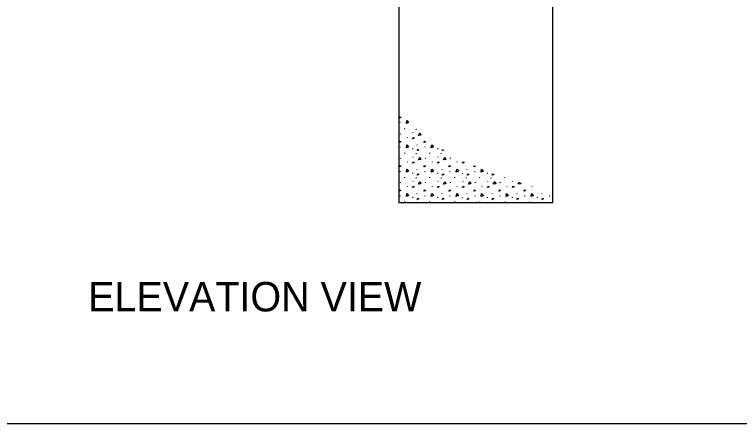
# Model space of a CAD drawing. Extents: x 99862 to 103680, y 99470 to 102076.
# Drawn here: x 100239 to 100829, y 100000 to 100332 of the extents above; entities that cross this region are included whole.
import ezdxf

# ---------------------------------------------------------------- set-up
doc = ezdxf.new("R2010")
doc.units = 0
for name, color, linetype in [('Level 1', 7, 'Continuous'), ('Level 12', 7, 'Continuous'), ('Level 20', 7, 'Continuous')]:
    doc.layers.add(name, color=color, linetype=linetype)

msp = doc.modelspace()

# ---------------------------------------------------------------- linework, layer by layer
at = {"layer": 'Level 1'}
msp.add_lwpolyline([(99862, 99999.5), (103151, 99999.5), (103151, 102075.5), (99862, 102075.5)], close=True, dxfattribs=at)
at = {"layer": 'Level 12'}
for p, q in [((100552.17, 100509.86), (100552.17, 100179.2)), ((100677.47, 100179.2), (100677.47, 100509.86)), ((100553.21, 100243.92), (100553.38, 100244.3)), ((100557.07, 100239), (100557.24, 100239.38)), ((100563.32, 100242.53), (100563.33, 100242.47)), ((100566.18, 100239), (100566.35, 100238.74)), ((100566.35, 100238.9), (100566.52, 100238.65)), ((100553.63, 100234.88), (100553.8, 100235.26)), ((100563.68, 100235.86), (100563.85, 100236.24)), ((100558.93, 100232.17), (100559.1, 100231.91)), ((100553.21, 100224.11), (100553.38, 100224.5)), ((100563.29, 100223.05), (100563.33, 100222.67)), ((100567.07, 100225.85), (100567.24, 100226.23)), ((100573.51, 100224.11), (100573.68, 100224.5)), ((100583.59, 100223.05), (100583.63, 100222.67)), ((100587.46, 100221.4), (100587.93, 100222.37)), ((100588.82, 100221.83), (100587.46, 100221.4)), ((100553.63, 100215.08), (100553.8, 100215.46)), ((100557.07, 100219.2), (100557.24, 100219.58)), ((100563.68, 100216.06), (100563.85, 100216.44)), ((100566.18, 100219.2), (100566.35, 100218.94)), ((100566.35, 100219.1), (100566.52, 100218.85)), ((100573.94, 100215.08), (100574.11, 100215.46)), ((100577.37, 100219.2), (100577.54, 100219.58)), ((100583.98, 100216.06), (100584.15, 100216.44)), ((100586.49, 100219.2), (100586.65, 100218.94)), ((100586.65, 100219.1), (100586.82, 100218.85)), ((100594.24, 100215.08), (100594.41, 100215.46)), ((100558.93, 100212.37), (100559.1, 100212.11)), ((100579.24, 100212.37), (100579.41, 100212.11)), ((100599.54, 100212.37), (100599.71, 100212.11)), ((100553.21, 100204.31), (100553.38, 100204.7)), ((100567.07, 100206.05), (100567.24, 100206.43)), ((100573.51, 100204.31), (100573.68, 100204.7)), ((100587.38, 100206.05), (100587.55, 100206.43)), ((100593.82, 100204.31), (100593.99, 100204.7)), ((100607.68, 100206.05), (100607.85, 100206.43)), ((100613.28, 100208.24), (100613.68, 100209.07)), ((100614.63, 100208.66), (100613.28, 100208.24)), ((100614.12, 100204.31), (100614.29, 100204.7)), ((100557.07, 100199.4), (100557.24, 100199.78)), ((100563.29, 100203.25), (100563.33, 100202.87)), ((100566.18, 100199.4), (100566.35, 100199.14)), ((100566.35, 100199.3), (100566.52, 100199.05)), ((100577.37, 100199.4), (100577.54, 100199.78)), ((100583.59, 100203.25), (100583.63, 100202.87)), ((100586.49, 100199.4), (100586.65, 100199.14)), ((100586.65, 100199.3), (100586.82, 100199.05)), ((100597.68, 100199.4), (100597.85, 100199.78)), ((100603.9, 100203.25), (100603.94, 100202.87)), ((100606.79, 100199.4), (100606.96, 100199.14)), ((100606.96, 100199.3), (100607.13, 100199.05)), ((100617.98, 100199.4), (100618.15, 100199.78)), ((100624.2, 100203.25), (100624.24, 100202.87)), ((100627.1, 100199.4), (100627.26, 100199.14)), ((100627.26, 100199.3), (100627.43, 100199.05)), ((100638.29, 100199.4), (100638.46, 100199.78)), ((100553.63, 100195.28), (100553.8, 100195.66)), ((100558.93, 100192.57), (100559.1, 100192.31)), ((100563.68, 100196.25), (100563.85, 100196.64)), ((100573.94, 100195.28), (100574.11, 100195.66)), ((100579.24, 100192.57), (100579.41, 100192.31)), ((100583.98, 100196.25), (100584.15, 100196.64)), ((100594.24, 100195.28), (100594.41, 100195.66)), ((100599.54, 100192.57), (100599.71, 100192.31)), ((100604.29, 100196.25), (100604.46, 100196.64)), ((100614.55, 100195.28), (100614.72, 100195.66)), ((100619.85, 100192.57), (100620.02, 100192.31)), ((100624.59, 100196.25), (100624.76, 100196.64)), ((100634.85, 100195.28), (100635.02, 100195.66)), ((100640.15, 100192.57), (100640.32, 100192.31)), ((100644.9, 100196.25), (100645.07, 100196.64)), ((100649.44, 100194.14), (100650.32, 100195.81)), ((100660.53, 100192.46), (100660.63, 100192.31)), ((100567.07, 100186.25), (100567.24, 100186.63)), ((100587.38, 100186.25), (100587.55, 100186.63)), ((100607.68, 100186.25), (100607.85, 100186.63)), ((100627.99, 100186.25), (100628.16, 100186.63)), ((100648.29, 100186.25), (100648.46, 100186.63)), ((100668.6, 100186.25), (100668.77, 100186.63)), ((100553.21, 100184.51), (100553.38, 100184.89)), ((100557.07, 100179.6), (100557.24, 100179.98)), ((100563.29, 100183.45), (100563.33, 100183.07)), ((100573.51, 100184.51), (100573.68, 100184.89)), ((100577.37, 100179.6), (100577.54, 100179.98)), ((100583.59, 100183.45), (100583.63, 100183.07)), ((100593.82, 100184.51), (100593.99, 100184.89)), ((100597.68, 100179.6), (100597.85, 100179.98)), ((100603.9, 100183.45), (100603.94, 100183.07)), ((100614.12, 100184.51), (100614.29, 100184.89)), ((100617.98, 100179.6), (100618.15, 100179.98)), ((100624.2, 100183.45), (100624.24, 100183.07)), ((100634.43, 100184.51), (100634.6, 100184.89)), ((100638.29, 100179.6), (100638.46, 100179.98)), ((100644.51, 100183.45), (100644.55, 100183.07)), ((100654.73, 100184.51), (100654.9, 100184.89)), ((100658.59, 100179.6), (100658.76, 100179.98)), ((100664.81, 100183.45), (100664.85, 100183.07)), ((100675.04, 100184.51), (100675.21, 100184.89)), ((100552.17, 100179.2), (100677.47, 100179.2)), ((100566.18, 100179.6), (100566.35, 100179.34)), ((100566.35, 100179.5), (100566.52, 100179.24)), ((100586.49, 100179.6), (100586.65, 100179.34)), ((100586.65, 100179.5), (100586.82, 100179.24)), ((100606.79, 100179.6), (100606.96, 100179.34)), ((100606.96, 100179.5), (100607.13, 100179.24)), ((100627.1, 100179.6), (100627.26, 100179.34)), ((100627.26, 100179.5), (100627.43, 100179.24)), ((100647.4, 100179.6), (100647.57, 100179.34)), ((100647.57, 100179.5), (100647.74, 100179.24)), ((100667.71, 100179.6), (100667.87, 100179.34)), ((100667.87, 100179.5), (100668.04, 100179.24))]:
    msp.add_line(p, q, dxfattribs=at)
for points in [[(100552.37, 100247.84), (100552.88, 100248.9), (100553.73, 100248.26), (100552.37, 100247.84)], [(100558.37, 100243.48), (100558.7, 100245.9), (100560.22, 100244.33), (100558.41, 100243.49)], [(100568.22, 100233.74), (100569.36, 100235.9), (100570.25, 100233.91), (100568.26, 100233.74)], [(100552.37, 100228.04), (100552.88, 100229.1), (100553.73, 100228.46), (100552.37, 100228.04)], [(100563.38, 100231.07), (100563.89, 100232.13), (100564.74, 100231.49), (100563.38, 100231.07)], [(100572.67, 100228.04), (100573.18, 100229.1), (100574.03, 100228.46), (100572.67, 100228.04)], [(100558.37, 100223.68), (100558.7, 100226.1), (100560.22, 100224.53), (100558.41, 100223.69)], [(100567.16, 100221.4), (100567.66, 100222.46), (100568.51, 100221.83), (100567.16, 100221.4)], [(100578.67, 100223.68), (100579.01, 100226.1), (100580.53, 100224.53), (100578.71, 100223.69)], [(100568.22, 100213.94), (100569.36, 100216.1), (100570.25, 100214.11), (100568.26, 100213.94)], [(100588.52, 100213.94), (100589.66, 100216.1), (100590.56, 100214.11), (100588.56, 100213.94)], [(100563.38, 100211.27), (100563.89, 100212.33), (100564.74, 100211.69), (100563.38, 100211.27)], [(100583.69, 100211.27), (100584.2, 100212.33), (100585.04, 100211.69), (100583.69, 100211.27)], [(100603.99, 100211.27), (100604.5, 100212.33), (100605.35, 100211.69), (100603.99, 100211.27)], [(100552.37, 100208.24), (100552.88, 100209.3), (100553.73, 100208.66), (100552.37, 100208.24)], [(100558.37, 100203.88), (100558.7, 100206.3), (100560.22, 100204.73), (100558.41, 100203.89)], [(100572.67, 100208.24), (100573.18, 100209.3), (100574.03, 100208.66), (100572.67, 100208.24)], [(100578.67, 100203.88), (100579.01, 100206.3), (100580.53, 100204.73), (100578.71, 100203.89)], [(100592.98, 100208.24), (100593.49, 100209.3), (100594.34, 100208.66), (100592.98, 100208.24)], [(100598.98, 100203.88), (100599.31, 100206.3), (100600.83, 100204.73), (100599.02, 100203.89)], [(100619.28, 100203.88), (100619.62, 100206.3), (100621.13, 100204.73), (100619.32, 100203.89)], [(100567.16, 100201.6), (100567.66, 100202.66), (100568.51, 100202.02), (100567.16, 100201.6)], [(100587.46, 100201.6), (100587.97, 100202.66), (100588.82, 100202.02), (100587.46, 100201.6)], [(100607.77, 100201.6), (100608.27, 100202.66), (100609.12, 100202.02), (100607.77, 100201.6)], [(100628.07, 100201.6), (100628.58, 100202.66), (100629.43, 100202.02), (100628.07, 100201.6)], [(100563.38, 100191.46), (100563.89, 100192.52), (100564.74, 100191.89), (100563.38, 100191.46)], [(100568.22, 100194.14), (100569.36, 100196.3), (100570.25, 100194.3), (100568.26, 100194.14)], [(100583.69, 100191.46), (100584.2, 100192.52), (100585.04, 100191.89), (100583.69, 100191.46)], [(100588.52, 100194.14), (100589.66, 100196.3), (100590.56, 100194.3), (100588.56, 100194.14)], [(100603.99, 100191.46), (100604.5, 100192.52), (100605.35, 100191.89), (100603.99, 100191.46)], [(100608.83, 100194.14), (100609.97, 100196.3), (100610.86, 100194.3), (100608.87, 100194.14)], [(100624.3, 100191.46), (100624.81, 100192.52), (100625.65, 100191.89), (100624.3, 100191.46)], [(100629.13, 100194.14), (100630.27, 100196.3), (100631.16, 100194.3), (100629.17, 100194.14)], [(100644.6, 100191.46), (100645.11, 100192.52), (100645.96, 100191.89), (100644.6, 100191.46)], [(100650.88, 100195.63), (100651.47, 100194.3), (100649.48, 100194.14)], [(100552.37, 100188.43), (100552.88, 100189.49), (100553.73, 100188.86), (100552.37, 100188.43)], [(100558.37, 100184.07), (100558.7, 100186.5), (100560.22, 100184.93), (100558.41, 100184.09)], [(100572.67, 100188.43), (100573.18, 100189.49), (100574.03, 100188.86), (100572.67, 100188.43)], [(100578.67, 100184.07), (100579.01, 100186.5), (100580.53, 100184.93), (100578.71, 100184.09)], [(100592.98, 100188.43), (100593.49, 100189.49), (100594.34, 100188.86), (100592.98, 100188.43)], [(100598.98, 100184.07), (100599.31, 100186.5), (100600.83, 100184.93), (100599.02, 100184.09)], [(100613.28, 100188.43), (100613.79, 100189.49), (100614.64, 100188.86), (100613.28, 100188.43)], [(100619.28, 100184.07), (100619.62, 100186.5), (100621.13, 100184.93), (100619.32, 100184.09)], [(100633.59, 100188.43), (100634.1, 100189.49), (100634.95, 100188.86), (100633.59, 100188.43)], [(100639.59, 100184.07), (100639.92, 100186.5), (100641.44, 100184.93), (100639.63, 100184.09)], [(100653.89, 100188.43), (100654.4, 100189.49), (100655.25, 100188.86), (100653.89, 100188.43)], [(100659.89, 100184.07), (100660.23, 100186.5), (100661.74, 100184.93), (100659.93, 100184.09)], [(100567.16, 100181.8), (100567.66, 100182.86), (100568.51, 100182.22), (100567.16, 100181.8)], [(100587.46, 100181.8), (100587.97, 100182.86), (100588.82, 100182.22), (100587.46, 100181.8)], [(100607.77, 100181.8), (100608.27, 100182.86), (100609.12, 100182.22), (100607.77, 100181.8)], [(100628.07, 100181.8), (100628.58, 100182.86), (100629.43, 100182.22), (100628.07, 100181.8)], [(100648.38, 100181.8), (100648.88, 100182.86), (100649.73, 100182.22), (100648.38, 100181.8)], [(100668.68, 100181.8), (100669.19, 100182.86), (100670.04, 100182.22), (100668.68, 100181.8)]]:
    msp.add_lwpolyline(points, dxfattribs=at)

# ---------------------------------------------------------------- texts
at = {"layer": 'Level 20'}
msp.add_text('ELEVATION VIEW', height=24, dxfattribs=at).set_placement((100299.49, 100090.64))

doc.saveas('drawing.dxf')
